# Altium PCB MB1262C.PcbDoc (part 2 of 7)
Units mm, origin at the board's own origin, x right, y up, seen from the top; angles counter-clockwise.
Board outline 208 x 250 mm, 6 copper layers (Top Layer, Layer 2, Layer 3, Layer 4, Layer 5, Bottom Layer), stack 1.596 mm thick; 483 components, 502 nets, 2134 pads, 1709 vias.
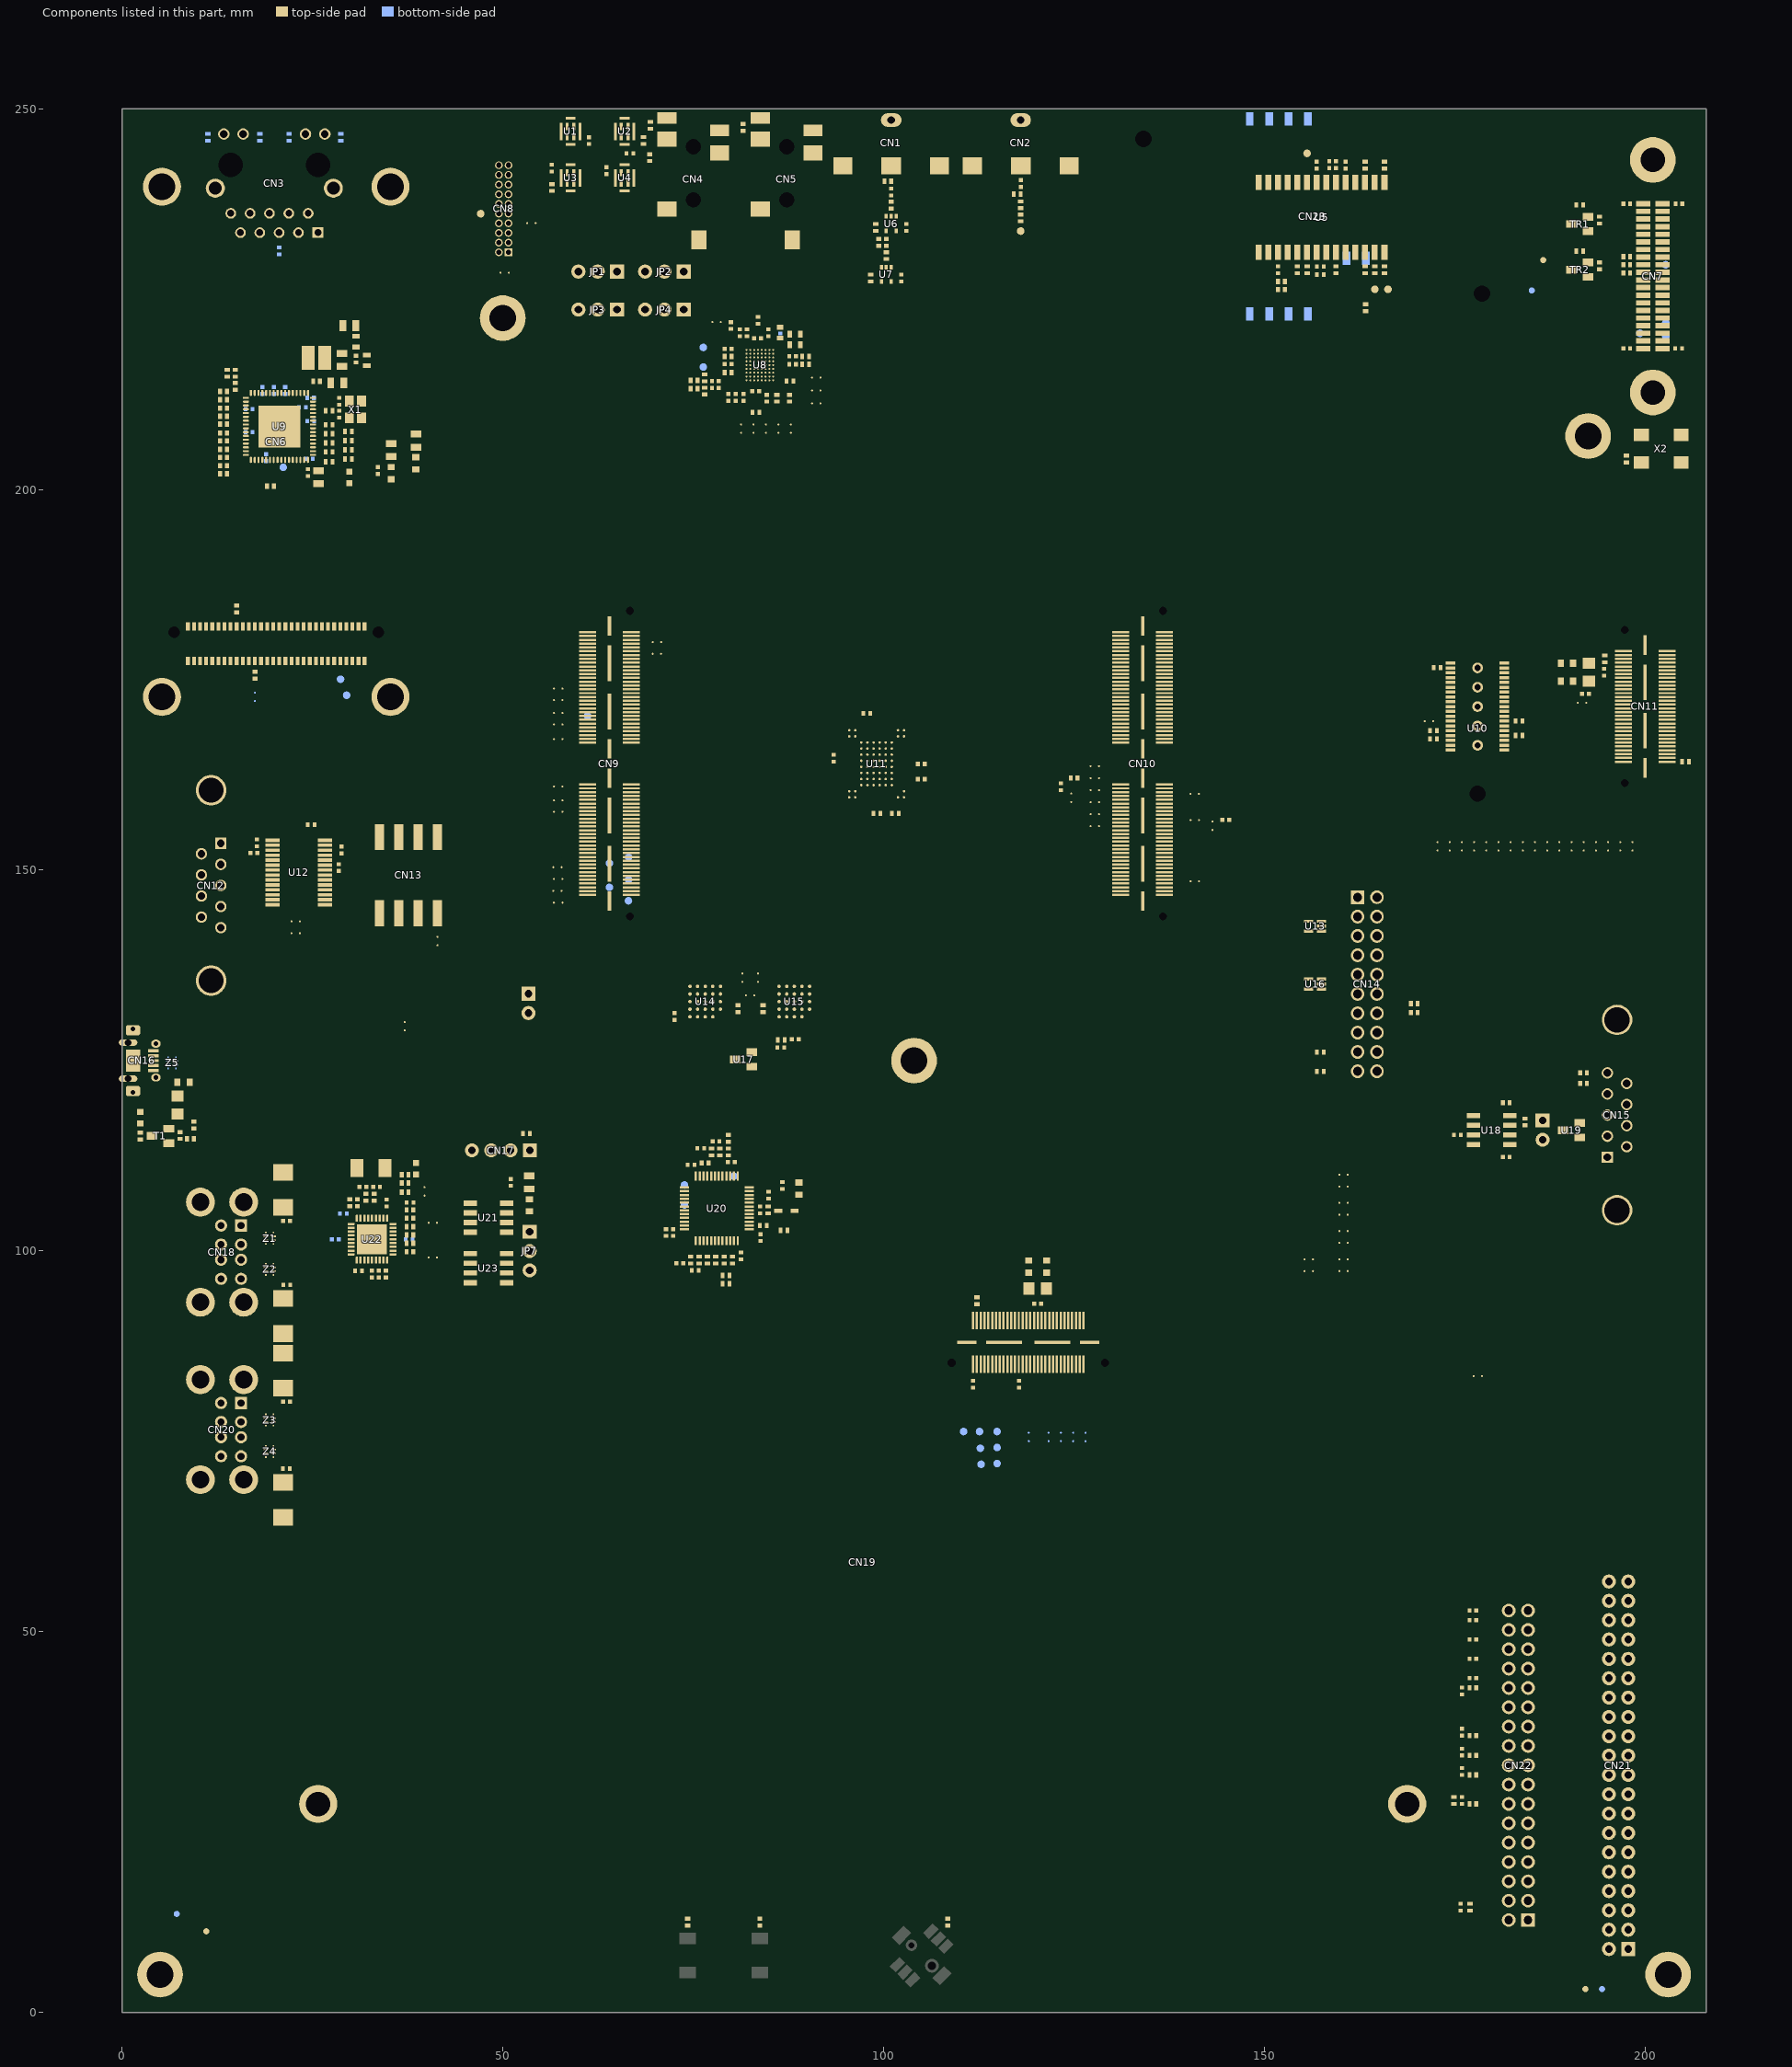
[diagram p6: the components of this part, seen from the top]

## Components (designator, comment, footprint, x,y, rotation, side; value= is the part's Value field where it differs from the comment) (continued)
C132 ".designator" C0402 29.067,104.935 r0 bottom value=100nF
C133 ".designator" C0402 37.7,101.55 r180 bottom value=100nF
C134 ".designator" C0402 28,101.55 r0 bottom value=100nF
CN1 ".designator" CON_SMD-RCA-SOCKET_CUI_RCJ-013-SMT 101,248.5 r270 top
CN2 ".designator" CON_SMD-RCA-SOCKET_CUI_RCJ-013-SMT 118,248.5 r270 top
CN3 ".designator" CON_RJ45_YD_48F-01GYDXNL_LED-P 20,250 r180 top locked
CN4 ".designator" CON_PHONE-JACK-3P5_HY_PJ3028B 75,250 r270 top value=PJ3028B-3_GR
CN5 ".designator" CON_PHONE-JACK-3P5_HY_PJ3028B 87.261,250 r270 top value="PJ-3028B-3 4P"
CN6 ".designator" CON_SAMTEC_ERF8-030-070-L-DV-TR_MOD-B2123A 20.25,179.75 r270 top locked
CN7 ".designator" CON_SAMTEC_CLM-120-02-L-D_Reverse-to-Camera 201,228 r0 top locked value=CLM-120-02-L-D
CN8 ".designator" CON_FCI_20021311-XXX20XXLF_MOD-MB1299 50.117,236.851 r270 top locked value="Receptacle 10X2 TH VT 1.27mm"
CN9 ".designator" CON_SAMTEC_QSH-060-01-L-D-A 64,164 r270 top locked
CN10 ".designator" CON_SAMTEC_QSH-060-01-L-D-A 134,164 r270 top locked
CN11 ".designator" CON_SAMTEC_QSH-030-01-F-D-A 200,171.5 r270 top locked value=QSH-030-01-F-D-A
CN12 ".designator" CON_DB9-MALE_TYCO_3-1634580-2 4.2,148 r270 top locked
CN13 ".designator" CON_SAMTEC_SSM-104-L-DH 37.625,149.35 r180 top locked value=SSM-104-L-DH
CN14 ".designator" CON_CVILUX_CH87-20-2-V-1-00 163.5,135.025 r270 top locked
CN15 ".designator" CON_DB9-MALE_TYCO_3-1634580-2 203.8,117.85 r90 top locked
CN16 ".designator" CON_USBMICROAB_MOLEX_47590-0001_H3 0,125 r270 top locked value=475900001
CN17 ".designator" CON_SAMTEC_TSW-104-07-G-S 49.75,113.219 r180 top locked value="Header 4 pins"
CN18 ".designator" CON_DUAL-USB-TYPE-A_CONEXCON_5600-3081 0,99.85 r270 top locked value="Dual USB Type A"
CN19 ".designator" CON_SAMTEC_QSH-030-01-F-D-A_LCD-MB1230 119,88 r180 top locked value=QSH-030-01-F-D-A
CN20 ".designator" CON_DUAL-USB-TYPE-A_CONEXCON_5600-3081 0,76.55 r270 top locked value="Dual USB Type A"
CN21 ".designator" CON_SAMTEC_TSW-120-07-G-D 196.5,32.475 r90 top locked value=TSW-120-07-G-D
CN22 ".designator" CON_SAMTEC_TST-117-01-T-D 183.35,32.475 r90 top locked value=BHFS03-34G01BT1
CN23 ".designator" CON_SMARTCARD_CONCRAFT_093A-65-08A 155,250 r0 bottom locked value=093A-65-08A
D1 ".designator" DIO_SOD323 87.25,105.3 r0 top
Designator1 ".designator" MOD_MB1263 64,164 r270 top locked
Designator2 ".designator" CARTOUCHE_STM_BOTTOM 43.172,-35.703 r0 top
Designator3 ".designator" CARTOUCHE_STM_TOP 43.097,-35.728 r0 top
H1 ".designator" PTH_M1261-3005-N_3P5X6_M3_H14 50,222.5 r180 bottom
H2 ".designator" PTH_M1261-3005-N_3P5X6_M3_H14 192.5,207 r180 bottom
H3 ".designator" PTH_M1261-3005-N_3P5X6_M3_H14 104,125 r180 bottom
H4 ".designator" PTH_M1261-3005-N_3P5X6_M3_H14 203,5 r180 bottom
H5 ".designator" PTH_M1261-3005-N_3P5X6_M3_H14 5,5 r180 bottom
JP1 ".designator" CON_SAMTEC_TSW-103-07-F-S 62.455,228.607 r180 top value="Header 3 pins"
JP2 ".designator" CON_SAMTEC_TSW-103-07-F-S 71.224,228.607 r180 top value="Header 3 pins"
JP3 ".designator" CON_SAMTEC_TSW-103-07-F-S 62.455,223.607 r180 top value="Header 3 pins"
JP4 ".designator" CON_SAMTEC_TSW-103-07-F-S 71.224,223.607 r180 top value="Header 3 pins"
JP5 ".designator" CON_SAMTEC_TSW-102-07-G-S 53.37,132.51 r270 top value=Jumper_2.54mm
JP6 ".designator" CON_SAMTEC_TSW-102-07-G-S 186.525,115.875 r270 top value=Jumper_2.54mm
JP7 ".designator" CON_SAMTEC_TSW-103-07-F-S 53.522,100 r270 top value="Header 3 pins"
L1 ".designator" L0603 38.56,203.436 r270 top value=100R
L2 ".designator" L0603 35.341,202.139 r270 top value=100R
L3 ".designator" L0603 189.725,177.175 r180 top value=600R
L4 ".designator" L0603 189.725,174.825 r180 top value=600R
L5 ".designator" FIL_0603_H065 8.074,122.143 r180 top value=120R
L6 ".designator" L0603 88.9,108.2 r270 top value=600R
L7 ".designator" FIL_0603_H065 53.48,106 r270 top value=26R
L8 ".designator" L0603 119.05,97.95 r270 top value=600R
L9 ".designator" L0603 121.4,97.95 r270 top value=600R
LD1 ".designator" LED_0603_GREEN 29.842,201.588 r90 top value="LED, Green, 0603"
LD2 ".designator" LED_0603_GREEN 2.395,117.514 r90 top value="LED, Green"
LD3 ".designator" LED_0603_RED 38.59,110.792 r90 top value="LED, Red, 0603"
LE1 ".designator" L1210_LQH 25.54,217.278 r0 top
MIRE1 ".designator" MIRE_PLACE_SMD_0P8MM 186.604,230.116 r270 top
MIRE2 ".designator" MIRE_PLACE_SMD_0P8MM 11.067,10.678 r270 top
MIRE3 ".designator" MIRE_PLACE_SMD_0P8MM 192.147,3.091 r270 top
MIRE4 "MIRE4" MIRE_PLACE_SMD_0P8MM 185.099,226.124 r90 bottom
MIRE5 "MIRE5" MIRE_PLACE_SMD_0P8MM 7.179,12.964 r90 bottom
MIRE6 "MIRE6" MIRE_PLACE_SMD_0P8MM 194.326,3.091 r90 bottom
R1 ".designator" R0402 69.359,247.804 r90 top value=0R
R2 ".designator" R0402 81.535,247.523 r270 top value=1K
R3 ".designator" R0402 68.475,245.8 r270 top value=10K
R4 ".designator" R0402 69.291,243.56 r270 top value=0R
R5 ".designator" R0402 163.225,242.575 r270 top value=100K
R6 ".designator" R0402 165.75,242.575 r90 top value=4K7
R7 ".designator" R0402 100.55,240.45 r0 top value=75
R8 ".designator" R0402 56.448,239.635 r90 top value=10K
R9 ".designator" R0402 117.55,238.775 r180 top value=110
R10 ".designator" R0402 118,237.375 r90 top value=210
R11 ".designator" R0402 101,237.325 r270 top value="100R 1%"
R12 ".designator" R0402 191.4,237.35 r0 top value=1K
R13 ".designator" R0402 118,235.65 r90 top value=0R
R14 ".designator" R0402 194,235.375 r270 top value=4K7
R15 ".designator" R0402 98.95,234.4 r270 top value=1M
R16 ".designator" R0402 99.35,232.425 r270 top value=0R
R17 ".designator" R0402 191.4,231.3 r0 top value=1K
R18 ".designator" R0402 100.35,230.7 r270 top value="100R 1%"
R19 ".designator" R0402 197.575,230.575 r0 top value=10K
R20 ".designator" R0402 194,229.35 r270 top value=4K7
R21 ".designator" R0402 197.575,229.5 r0 top value=1K
R22 ".designator" R0402 154.325,228.85 r270 top value=100K
R23 ".designator" R0402 155.6,228.85 r270 top value=100K
R24 ".designator" R0402 159.4,228.85 r90 top value=100K
R25 ".designator" R0402 163.225,228.85 r270 top value=0R
R26 ".designator" R0402 164.5,228.85 r90 top value=10K
R27 ".designator" R0402 165.75,228.85 r90 top value=10K
R28 ".designator" R0402 197.575,228.425 r0 top value=1K
R29 ".designator" R0402 98.3,227.75 r270 top value=1M
R30 ".designator" R0402 152.225,227.3 r180 top value=10K
R31 ".designator" R0402 152.225,226.25 r0 top value=10K
R32 ".designator" R0402 163.298,223.855 r90 top value=100K
R33 ".designator" R0603 30.731,219.407 r270 top value=0R_0603
R34 ".designator" R0603 32.133,216.939 r90 top value=0R_0603
R35 ".designator" R0402 79.575,217.475 r180 top value=2K2
R36 ".designator" R0402 89.75,217.475 r180 top value="20R 1%"
R37 ".designator" R0402 89.75,216.425 r180 top value="20R 1%"
R38 ".designator" R0402 13.825,215.25 r90 top value=4K7
R39 ".designator" R0402 14.875,215.25 r270 top value=4K7
R40 ".designator" R0402 79.575,215.35 r0 top value=4K7
R41 ".designator" R0402 76.504,214.638 r270 top value=1K
R42 ".designator" R0402 75.104,214.313 r180 top value="180R 1%"
R43 ".designator" R0402 87.711,214.22 r0 top value=1K
R44 ".designator" R0402 25.544,214.182 r180 top value="22R 1%"
R45 ".designator" R0402 14.875,213.525 r270 top value=0R
R46 ".designator" R0402 75.104,213.238 r180 top value="180R 1%"
R47 ".designator" R0402 76.504,212.913 r270 top value=1K
R48 ".designator" R0402 13.325,212.875 r0 top value="22R 1%"
R49 ".designator" R0402 85.98,211.975 r270 top value=0R
R50 ".designator" R0402 87.633,211.975 r270 top value=0R
R51 ".designator" R0402 13.325,211.775 r0 top value="22R 1%"
R52 ".designator" R0402 13.325,210.675 r0 top value="22R 1%"
R53 ".designator" R0402 27.189,210.321 r180 top value=0R
R54 ".designator" R0402 83.242,210.125 r0 top value=0R
R55 ".designator" R0402 13.325,209.6 r0 top value="22R 1%"
R56 ".designator" R0402 13.325,208.575 r0 top value=0R
R57 ".designator" R0402 27.187,208.497 r180 top value=2K49
R58 ".designator" R0402 29.737,207.628 r0 top value=4K7
R59 ".designator" R0402 13.325,207.4 r180 top value=4K7
R60 ".designator" R0402 27.187,207.306 r0 top value=1K5
R61 ".designator" R0402 29.737,206.413 r0 top value=4K7
R62 ".designator" R0402 13.325,206.375 r180 top value=4K7
R63 ".designator" R0402 27.187,206.116 r0 top value=1K5
R64 ".designator" R0402 13.325,205.275 r180 top value=4K7
R65 ".designator" R0402 29.737,205.197 r180 top value=0R
R66 ".designator" R0402 27.187,204.925 r0 top value=1K5
R67 ".designator" R0402 197.525,204 r270 top value=10K
R68 ".designator" R0402 13.325,204.2 r180 top value=4K7
R69 ".designator" R0402 29.737,203.981 r180 top value=0R
R70 ".designator" R0402 27.187,203.634 r0 top value="510R 1%"
R71 ".designator" R0402 13.325,203.125 r180 top value=4K7
R72 ".designator" R0402 13.325,202.05 r180 top value=4K7
R73 ".designator" R0402 19.486,200.412 r180 top value=0R
R74 ".designator" R0402 15.046,184.311 r270 top value=0R
R75 ".designator" R0402 194.675,177.75 r270 top value=0R
R76 ".designator" R0402 172.688,176.613 r180 top value=0R
R77 ".designator" R0402 17.457,175.615 r90 top value=0R
R78 ".designator" R0402 183.425,169.6 r180 top value=10K
R79 ".designator" R0402 172.2,168.325 r180 top value=10K
R80 ".designator" R0402 183.425,167.7 r180 top value=10K
R81 ".designator" R0402 172.2,167.25 r180 top value=10K
R82 ".designator" R0402 205.3,164.25 r0 top value=0R
R83 ".designator" R0402 125.009,162.096 r180 top value=0R
R84 ".designator" R0402 99.125,157.45 r0 top value=10K
R85 ".designator" R0402 101.525,157.45 r0 top value=10K
R86 ".designator" R0402 169.675,132.5 r180 top value=10K
R87 ".designator" R0402 84.187,131.82 r90 top value=10K
R88 ".designator" R0402 80.881,131.82 r90 top value=10K
R89 ".designator" R0402 169.675,131.3 r0 top value=10K
R90 ".designator" R0402 86.557,127.717 r0 top value=15K
R91 ".designator" R0402 157.325,126.125 r180 top value=10K
R92 ".designator" R0402 157.325,123.575 r180 top value=10K
R93 ".designator" R0402 191.9,123.4 r0 top value=0R
R94 ".designator" R0402 191.9,122 r0 top value=1K
R95 ".designator" R0402 181.75,119.475 r0 top value=10K
R96 ".designator" R0402 184.2,116.95 r90 top value="120R 1%"
R97 ".designator" R0402 9.43,116.537 r90 top value=0R
R98 ".designator" R0402 7.621,115.164 r90 top value=10K
R99 ".designator" R0402 53.097,115.42 r180 top value=0R
R100 ".designator" R0402 2.384,115.097 r270 top value=330R
R101 ".designator" R0402 79.6,114.8 r90 top value=10K
R102 ".designator" R0402 8.987,114.72 r180 top value=47K
R103 ".designator" R0402 77.4,113 r90 top value=0R
R104 ".designator" R0402 78.5,113 r90 top value=0R
R105 ".designator" R0402 79.6,113 r270 top value=10K
R106 ".designator" R0402 76.565,111.549 r180 top value="100R 1%"
R107 ".designator" R0402 37.175,110.015 r0 top value=1K
R108 ".designator" R0402 37.175,108.93 r180 top value=100K
R109 ".designator" R0402 37.175,107.736 r180 top value=10K
R110 ".designator" R0402 32.012,107.052 r270 top value=0R
R111 ".designator" R0402 33.112,107.052 r270 top value=0R
R112 ".designator" R0402 29.913,106.346 r90 top value=12K
R113 ".designator" R0402 84.825,105.4 r90 top value=10K
R114 ".designator" R0402 37.806,105.405 r180 top value=100K
R115 ".designator" R0402 37.806,104.305 r0 top value=100K
R116 ".designator" R0402 84.21,103.34 r180 top value=47K
R117 ".designator" R0402 37.806,103.205 r180 top value=100K
R118 ".designator" R0402 86.925,102.71 r180 top value=0R
R119 ".designator" R0402 37.806,102.105 r0 top value=100K
R120 ".designator" R0402 37.806,101.005 r0 top value=100K
R121 ".designator" R0402 37.806,99.905 r180 top value=100K
R122 ".designator" R0402 74.66,98.823 r270 top value=0R
R123 ".designator" R0402 75.76,98.823 r270 top value=0R
R124 ".designator" R0402 76.86,98.823 r90 top value=0R
R125 ".designator" R0402 77.96,98.823 r90 top value=0R
R126 ".designator" R0402 79.06,98.823 r90 top value="510R 1%"
R127 ".designator" R0402 80.16,98.823 r90 top value=0R
R128 ".designator" R0402 79.31,96.798 r180 top value=10K
R129 ".designator" R0402 79.31,95.698 r180 top value=1K
R130 ".designator" R0402 112.25,93.475 r90 top value=10K
R131 ".designator" R0402 177.368,42.644 r180 top value=0R
R132 ".designator" R0402 177.368,36.38 r0 top value=0R
R133 ".designator" R0402 177.368,33.765 r0 top value=0R
R134 ".designator" R0402 177.368,31.201 r0 top value=0R
R135 ".designator" R0402 174.873,27.844 r270 top value=100K
R136 ".designator" R0402 177.368,27.394 r180 top value=0R
R137 ".designator" R0402 176.98,13.835 r90 top value=3K3
R138 ".designator" R0402 108.426,11.886 r270 top value=100R
R139 ".designator" R0402 74.25,11.875 r270 top value=10K
R140 ".designator" R0402 28.722,246.23 r270 bottom value="510R 1%"
R141 ".designator" R0402 21.929,246.23 r90 bottom value=4K7
R142 ".designator" R0402 11.285,246.223 r90 bottom value=4K7
R143 ".designator" R0402 18.096,246.223 r270 bottom value="510R 1%"
SB1 ".designator" SOLDER-BRIDGE_R0603-0R 53.805,234.949 r180 top value=SB_OFF
SB2 ".designator" SOLDER-BRIDGE_R0603-0R 50.197,228.46 r0 top value=SB_ON
SB3 ".designator" SOLDER-BRIDGE_R0603-0R 78.008,221.965 r0 top value=SB_ON
SB4 ".designator" SOLDER-BRIDGE_R0603-0R 91.2,214.7 r180 top value=SB_OFF
SB5 ".designator" SOLDER-BRIDGE_R0603-0R 91.2,213 r180 top value=SB_ON
SB6 ".designator" SOLDER-BRIDGE_R0603-0R 91.2,211.3 r180 top value=SB_ON
SB7 ".designator" SOLDER-BRIDGE_R0603-0R 81.291,207.934 r90 top value=SB_ON
SB8 ".designator" SOLDER-BRIDGE_R0603-0R 84.556,207.934 r90 top value=SB_ON
SB9 ".designator" SOLDER-BRIDGE_R0603-0R 86.189,207.934 r90 top value=SB_ON
SB10 ".designator" SOLDER-BRIDGE_R0603-0R 87.821,207.934 r90 top value=SB_ON
SB11 ".designator" SOLDER-BRIDGE_R0603-0R 82.923,207.934 r90 top value=SB_ON
SB12 ".designator" SOLDER-BRIDGE_R0603-0R 70.293,179.951 r180 top value=SB_OFF
SB13 ".designator" SOLDER-BRIDGE_R0603-0R 70.293,178.413 r180 top value=SB_OFF
SB14 ".designator" SOLDER-BRIDGE_R0603-0R 57.217,173.842 r0 top value=SB_OFF
SB15 ".designator" SOLDER-BRIDGE_R0603-0R 57.217,172.338 r0 top value=SB_ON
SB16 ".designator" SOLDER-BRIDGE_R0603-0R 191.65,172 r0 top value=SB_ON
SB17 ".designator" SOLDER-BRIDGE_R0603-0R 57.217,170.634 r0 top value=SB_ON
SB18 ".designator" SOLDER-BRIDGE_R0603-0R 171.65,169.575 r180 top value=SB_OFF
SB19 ".designator" SOLDER-BRIDGE_R0603-0R 57.217,169.129 r0 top value=SB_OFF
SB20 ".designator" SOLDER-BRIDGE_R0603-0R 57.217,167.225 r0 top value=SB_OFF
SB21 ".designator" SOLDER-BRIDGE_R0603-0R 127.683,163.672 r0 top value=SB_OFF
SB22 ".designator" SOLDER-BRIDGE_R0603-0R 127.683,162.093 r0 top value=SB_OFF
SB23 ".designator" SOLDER-BRIDGE_R0603-0R 57.217,160.998 r0 top value=SB_OFF
SB24 ".designator" SOLDER-BRIDGE_R0603-0R 127.683,160.513 r0 top value=SB_OFF
SB25 ".designator" SOLDER-BRIDGE_R0603-0R 124.615,159.561 r270 top value=SB_OFF
SB26 ".designator" SOLDER-BRIDGE_R0603-0R 140.893,160.026 r180 top value=SB_OFF
SB27 ".designator" SOLDER-BRIDGE_R0603-0R 57.217,159.163 r0 top value=SB_ON
SB28 ".designator" SOLDER-BRIDGE_R0603-0R 127.683,158.933 r0 top value=SB_OFF
SB29 ".designator" SOLDER-BRIDGE_R0603-0R 57.217,157.692 r0 top value=SB_OFF
SB30 ".designator" SOLDER-BRIDGE_R0603-0R 127.683,157.354 r0 top value=SB_OFF
SB31 ".designator" SOLDER-BRIDGE_R0603-0R 143.186,155.887 r270 top value=SB_OFF
SB32 ".designator" SOLDER-BRIDGE_R0603-0R 140.903,156.582 r180 top value=SB_OFF
SB33 ".designator" SOLDER-BRIDGE_R0603-0R 127.683,155.774 r0 top value=SB_OFF
SB34 ".designator" SOLDER-BRIDGE_R0603-0R 198.326,153.092 r90 top value=SB_ON
SB35 ".designator" SOLDER-BRIDGE_R0603-0R 174.326,153.092 r90 top value=SB_ON
SB36 ".designator" SOLDER-BRIDGE_R0603-0R 182.326,153.092 r90 top value=SB_ON
SB37 ".designator" SOLDER-BRIDGE_R0603-0R 196.726,153.092 r90 top value=SB_ON
SB38 ".designator" SOLDER-BRIDGE_R0603-0R 172.726,153.092 r90 top value=SB_ON
SB39 ".designator" SOLDER-BRIDGE_R0603-0R 177.526,153.092 r90 top value=SB_ON
SB40 ".designator" SOLDER-BRIDGE_R0603-0R 179.126,153.092 r90 top value=SB_ON
SB41 ".designator" SOLDER-BRIDGE_R0603-0R 180.726,153.092 r90 top value=SB_ON
SB42 ".designator" SOLDER-BRIDGE_R0603-0R 183.926,153.092 r90 top value=SB_ON
SB43 ".designator" SOLDER-BRIDGE_R0603-0R 185.526,153.092 r90 top value=SB_ON
SB44 ".designator" SOLDER-BRIDGE_R0603-0R 188.726,153.092 r90 top value=SB_ON
SB45 ".designator" SOLDER-BRIDGE_R0603-0R 190.326,153.092 r90 top value=SB_ON
SB46 ".designator" SOLDER-BRIDGE_R0603-0R 191.926,153.092 r90 top value=SB_ON
SB47 ".designator" SOLDER-BRIDGE_R0603-0R 193.526,153.092 r90 top value=SB_ON
SB48 ".designator" SOLDER-BRIDGE_R0603-0R 195.126,153.092 r90 top value=SB_ON
SB49 ".designator" SOLDER-BRIDGE_R0603-0R 175.926,153.092 r90 top value=SB_ON
SB50 ".designator" SOLDER-BRIDGE_R0603-0R 187.126,153.092 r90 top value=SB_ON
SB51 "SB47" SOLDER-BRIDGE_R0603-0R 57.217,150.392 r180 top value=SB_ON
SB52 ".designator" SOLDER-BRIDGE_R0603-0R 57.217,148.842 r0 top value=SB_OFF
SB53 ".designator" SOLDER-BRIDGE_R0603-0R 140.903,148.561 r180 top value=SB_OFF
SB54 ".designator" SOLDER-BRIDGE_R0603-0R 57.217,147.292 r180 top value=SB_ON
SB55 ".designator" SOLDER-BRIDGE_R0603-0R 57.217,145.742 r0 top value=SB_OFF
SB56 ".designator" SOLDER-BRIDGE_R0603-0R 22.85,143.275 r180 top value=SB_OFF
SB57 ".designator" SOLDER-BRIDGE_R0603-0R 22.85,141.725 r180 top value=SB_ON
SB58 ".designator" SOLDER-BRIDGE_R0603-0R 41.425,140.75 r270 top value=SB_OFF
SB59 ".designator" SOLDER-BRIDGE_R0603-0R 81.455,135.944 r270 top value=SB_ON
SB60 ".designator" SOLDER-BRIDGE_R0603-0R 83.508,135.944 r270 top value=SB_ON
SB61 ".designator" SOLDER-BRIDGE_R0603-0R 82.515,133.566 r180 top value=SB_OFF
SB62 ".designator" SOLDER-BRIDGE_R0603-0R 37.11,129.566 r270 top value=SB_ON
SB63 ".designator" SOLDER-BRIDGE_R0603-0R 160.437,110.023 r180 top value=SB_OFF
SB64 ".designator" SOLDER-BRIDGE_R0603-0R 39.7,107.875 r270 top
SB65 ".designator" SOLDER-BRIDGE_R0603-0R 160.436,108.472 r180 top value=SB_OFF
SB66 ".designator" SOLDER-BRIDGE_R0603-0R 160.437,106.321 r180 top value=SB_OFF
SB67 ".designator" SOLDER-BRIDGE_R0603-0R 160.436,104.769 r180 top value=SB_OFF
SB68 ".designator" SOLDER-BRIDGE_R0603-0R 40.855,103.712 r180 top value=SB_OFF
SB69 ".designator" SOLDER-BRIDGE_R0603-0R 160.437,102.618 r180 top value=SB_OFF
SB70 ".designator" SOLDER-BRIDGE_R0603-0R 160.436,101.067 r180 top value=SB_OFF
SB71 ".designator" SOLDER-BRIDGE_R0603-0R 40.855,99.157 r180 top value=SB_OFF
SB72 ".designator" SOLDER-BRIDGE_R0603-0R 155.876,98.915 r180 top value=SB_OFF
SB73 ".designator" SOLDER-BRIDGE_R0603-0R 160.437,98.915 r180 top value=SB_OFF
SB74 ".designator" SOLDER-BRIDGE_R0603-0R 155.87,97.364 r180 top value=SB_OFF
SB75 ".designator" SOLDER-BRIDGE_R0603-0R 160.436,97.364 r180 top value=SB_OFF
SB76 ".designator" SOLDER-BRIDGE_R0603-0R 178.065,83.591 r180 top value=SB_OFF
SB77 ".designator" SOLDER-BRIDGE_R0603-0R 17.457,172.709 r90 bottom value=SB_ON
SB78 "SB73" SOLDER-BRIDGE_R0603-0R 126.525,75.625 r270 bottom value=SB_ON
SB79 "SB74" SOLDER-BRIDGE_R0603-0R 124.9,75.625 r270 bottom value=SB_ON
SB80 "SB75" SOLDER-BRIDGE_R0603-0R 123.275,75.625 r270 bottom value=SB_ON
SB81 "SB76" SOLDER-BRIDGE_R0603-0R 121.65,75.625 r270 bottom value=SB_ON
SB82 "SB77" SOLDER-BRIDGE_R0603-0R 119.05,75.625 r270 bottom value=SB_ON
T1 ".designator" NPN_SOT23 5.045,115.111 r90 top value=BSR14
TP1 ".designator" TP_SMD_1MM 155.6,244.125 r0 top value=TP
TP2 ".designator" TP_SMD_1MM 47.099,236.199 r270 top value=TP
TP3 ".designator" TP_SMD_1MM 118,233.925 r0 top value=TP
TP4 ".designator" TP_SMD_1MM 164.5,226.275 r0 top value=TP
TP5 ".designator" TP_SMD_1MM 166.225,226.275 r0 top value=TP
TP6 ".designator" TP_SMD_1MM 202.675,229.5 r0 bottom value=TP
TP7 ".designator" TP_SMD_1MM 202.7,221.925 r0 bottom value=TP
TP8 ".designator" TP_SMD_1MM 199.3,220.5 r0 bottom value=TP
TP9 ".designator" TP_SMD_1MM 202.7,220.075 r0 bottom value=TP
TP10 "TP10" TP_SMD_1MM 76.322,218.644 r90 bottom value=TP
TP11 ".designator" TP_SMD_1MM 76.322,216.069 r90 bottom value=TP
TP12 ".designator" TP_SMD_1MM 21.169,202.901 r0 bottom value=TP
TP13 ".designator" TP_SMD_1MM 28.7,175.075 r0 bottom value=TP
TP14 ".designator" TP_SMD_1MM 29.5,172.975 r0 bottom value=TP
TP15 ".designator" TP_SMD_1MM 61.125,170.275 r0 bottom value=TP
TP16 "TP16" TP_SMD_1MM 66.508,151.703 r180 bottom value=TP
TP17 "TP17" TP_SMD_1MM 63.991,150.92 r180 bottom value=TP
TP18 "TP18" TP_SMD_1MM 66.508,148.752 r180 bottom value=TP
TP19 "TP19" TP_SMD_1MM 63.991,147.752 r180 bottom value=TP
TP20 "TP20" TP_SMD_1MM 66.492,145.985 r180 bottom value=TP
TP21 ".designator" TP_SMD_1MM 80.35,109.825 r0 bottom value=TP
TP22 ".designator" TP_SMD_1MM 73.85,108.675 r0 bottom value=TP
TP23 ".designator" TP_SMD_1MM 73.85,106.05 r0 bottom value=TP
TP24 ".designator" TP_SMD_1MM 114.9,76.3 r0 bottom value=TP
TP25 ".designator" TP_SMD_1MM 112.6,76.3 r0 bottom value=TP
TP26 ".designator" TP_SMD_1MM 110.5,76.3 r0 bottom value=TP
TP27 ".designator" TP_SMD_1MM 114.9,74.2 r0 bottom value=TP
TP28 ".designator" TP_SMD_1MM 112.7,74.1 r0 bottom value=TP
TP29 ".designator" TP_SMD_1MM 114.9,72.1 r0 bottom value=TP
TP30 ".designator" TP_SMD_1MM 112.8,72 r0 bottom value=TP
TR1 ".designator" MOS_SOT23 191.4,234.85 r90 top value=BSN20
TR2 ".designator" MOS_SOT23 191.4,228.85 r90 top value=BSN20
U1 ".designator" MIC_HCLGA_3X4X1_4LD 58.888,247 r0 top locked value=MP34DT01TR-M
U2 ".designator" MIC_HCLGA_3X4X1_4LD 66,247 r0 top locked value=MP34DT01TR-M
U3 ".designator" MIC_HCLGA_3X4X1_4LD 58.888,240.904 r180 top locked value=MP34DT01TR-M
U4 ".designator" MIC_HCLGA_3X4X1_4LD 66,240.904 r180 top locked value=MP34DT01TR-M
U5 ".designator" ICC_SO28_18P10X7P60_P127 157.5,235.725 r180 top locked
U6 ".designator" DIO_SOT353 101,234.9 r180 top
U7 ".designator" DIO_SOT353 100.35,228.25 r180 top
U8 ".designator" ICC_W-CSP-BGA72_4P511X4P023_P050 83.75,216.325 r90 top locked value=WM8994ECS/R
U9 ".designator" ICC_QFN64-EPAD_9X9_P050 20.675,208.275 r270 top locked
U10 ".designator" CON_MICTOR_TYCO_2-5767004-2 177.985,171.485 r270 top locked
U11 ".designator" ICC_VFBGA63_9X11_P080 99.075,163.975 r180 top locked
U12 ".designator" ICC_SSOP28_10P2X5P3_P065 23.2,149.7 r270 top value=ST3241EBPR
U13 ".designator" ESD_SOT323-5L 156.65,142.65 r90 top locked
U14 ".designator" ICC_BGA24_5X5-BALL-ARRAY_6X8_P1 76.575,132.75 r180 top
U15 ".designator" ICC_BGA24_5X5-BALL-ARRAY_6X8_P1 88.275,132.75 r180 top
U16 ".designator" ESD_SOT323-5L 156.65,135.05 r90 top locked
U17 ".designator" MOS_SOT23 81.6,125.15 r90 top
U18 ".designator" ICC_SO8_5X4_P127 179.825,115.875 r270 top value=MCP2562FDT-H/SN
U19 ".designator" ESD_SOT23 190.3,115.85 r90 top value=ESDCAN24-2BLY
U20 ".designator" ICC_LQFP48_7X7_P050 78.1,105.6 r90 top value=STM32L152CCT6
U21 ".designator" ICC_SO8_5X4_P127 48.115,104.387 r90 top value=STMPS2252MTR
U22 ".designator" ICC_QFN36-EPAD_6X6_P050 32.825,101.55 r270 top value=USB2514B-AEZC
U23 ".designator" ICC_SO8_5X4_P127 48.115,97.749 r90 top value=STMPS2252MTR
X1 ".designator" CRY_NX3225HA_4P 30.65,210.5 r90 top value=25MHz
X2 ".designator" OSC_PLE_SM77H-SERIES_7X5_H1P73_4P 202.1,205.35 r0 top
X3 ".designator" CRY_TXC_7A-SERIES_5X3P2_H1P2_2P 32.67,110.902 r180 top value=24MHz
Z1 ".designator" ESD_UQFN-8L_2P5X1P2_P050 19.392,101.674 r270 top value=ECMF02-4CMX8
Z2 ".designator" ESD_UQFN-8L_2P5X1P2_P050 19.392,97.599 r270 top value=ECMF02-4CMX8
Z3 ".designator" ESD_UQFN-8L_2P5X1P2_P050 19.392,77.812 r270 top value=ECMF02-4CMX8
Z4 ".designator" ESD_UQFN-8L_2P5X1P2_P050 19.392,73.687 r270 top value=ECMF02-4CMX8
Z5 "Z1" ESD_UQFN-8L_2P5X1P2_P050 6.574,124.713 r90 bottom value=ECMF02-4CMX8

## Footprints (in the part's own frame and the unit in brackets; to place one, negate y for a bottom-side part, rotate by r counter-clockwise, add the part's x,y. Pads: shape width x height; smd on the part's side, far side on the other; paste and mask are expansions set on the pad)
C0402 [mm]
  rect 0.51x0.56 smd mask+0.05: 1(-0.45,0) 2(0.45,0)
  silkscreen extent -0.72,-0.35 0.72,0.35, body extent -0.5,-0.3 0.5,0.3, height 0.4
C0603 [mm]
  rect 0.64x0.89 smd mask+0.05: 1(-0.7,0) 2(0.7,0)
  silkscreen extent -1.05,-0.55 1.02,0.55, body extent -0.9,-0.5 0.9,0.5, height 1.4
C0805 [mm]
  rect 0.9x1.4 smd mask+0.05: 1(-0.85,0) 2(0.85,0)
  silkscreen extent -1.3,-0.77 1.3,0.77, body extent -1.1,-0.7 1.1,0.7, height 1.35
CARTOUCHE_STM_BOTTOM [mm]
CARTOUCHE_STM_TOP [mm]
CON_CVILUX_CH87-20-2-V-1-00 [mm]
  rect 1.8x1.8 hole 1.2 mask+0.05: 1(-11.43,-1.27)
  round 1.8 hole 1.2 mask+0.05: 2(-11.43,1.27) 3(-8.89,-1.27) 4(-8.89,1.27) 5(-6.35,-1.27) 6(-6.35,1.27) 7(-3.81,-1.27) 8(-3.81,1.27) 9(-1.27,-1.27) 10(-1.27,1.27) 11(1.27,-1.27) 12(1.27,1.27) 13(3.81,-1.27) 14(3.81,1.27) 15(6.35,-1.27) 16(6.35,1.27) 17(8.89,-1.27) 18(8.89,1.27) 19(11.43,-1.27) 20(11.43,1.27)
  silkscreen extent -16.51,-4.55 16.51,4.55, body extent -16.51,-4.57 16.51,4.57, height 9.86
CON_DB9-MALE_TYCO_3-1634580-2 [mm]
  rect 1.5x1.5 / inner round 1.5 / far side rect 1.5x1.5 hole 1 mask+0.05: 1(-5.54,8.77)
  round 1.5 hole 1 mask+0.05: 2(-2.77,8.77) 3(0,8.77) 4(2.77,8.77) 5(5.54,8.77) 6(-4.155,6.23) 7(-1.385,6.23) 8(1.385,6.23) 9(4.155,6.23)
  round 4 hole 3.3 mask+0.05: MT1(-12.5,7.5) MT2(12.5,7.5)
  silkscreen extent -15.5,-10.3 15.5,10.6, body extent -15.5,-10.3 15.5,10.6, height 13.8
CON_DUAL-USB-TYPE-A_CONEXCON_5600-3081 [mm]
  round 1.6 hole 0.92: B1(-3.5,13.01) B2(-1,13.01) B3(1,13.01) B4(3.5,13.01) T2(-1,15.63) T3(1,15.63) T4(3.5,15.63)
  round 3.8 hole 2.33: CH1(6.57,10.3) CH2(-6.57,10.3) CH3(-6.57,15.98) CH4(6.57,15.98)
  rect 1.6x1.6 hole 0.92: T1(-3.5,15.63)
  silkscreen extent -7.3,-0.4 7.3,17.85, body extent -7.82,-0.6 7.88,17.85, height 16.2
CON_FCI_20021311-XXX20XXLF_MOD-MB1299 [mm] "MB1299 MICROPHONE MEMS"
  rect 1x1 / inner round 1 / far side rect 1x1 hole 0.7 mask+0.05: 1(5.715,0.635)
  round 1 hole 0.7 mask+0.05: 2(5.715,-0.635) 3(4.445,0.635) 4(4.445,-0.635) 5(3.175,0.635) 6(3.175,-0.635) 7(1.905,0.635) 8(1.905,-0.635) 9(0.635,0.635) 10(0.635,-0.635) 11(-0.635,0.635) 12(-0.635,-0.635) 13(-1.905,0.635) 14(-1.905,-0.635) 15(-3.175,0.635) 16(-3.175,-0.635) 17(-4.445,0.635) 18(-4.445,-0.635) 19(-5.715,0.635) 20(-5.715,-0.635)
  silkscreen extent -9.13,-6.99 9.27,7.01, body extent -9.13,-6.99 9.27,7.01, height 6.9
CON_MICTOR_TYCO_2-5767004-2 [mm]
  rect 0.43x1.27 smd mask+0.05: 1(5.715,3.53) 2(5.715,-3.53) 3(5.08,3.53) 4(5.08,-3.53) 5(4.445,3.53) 6(4.445,-3.53) 7(3.81,3.53) 8(3.81,-3.53) 9(3.175,3.53) 10(3.175,-3.53) 11(2.54,3.53) 12(2.54,-3.53) 13(1.905,3.53) 14(1.905,-3.53) 15(1.27,3.53) 16(1.27,-3.53) 17(0.635,3.53) 18(0.635,-3.53) 19(0,3.53) 20(0,-3.53) 21(-0.635,3.53) 22(-0.635,-3.53) 23(-1.27,3.53) 24(-1.27,-3.53) 25(-1.905,3.53) 26(-1.905,-3.53) 27(-2.54,3.53) 28(-2.54,-3.53) 29(-3.175,3.53) 30(-3.175,-3.53) 31(-3.81,3.53) 32(-3.81,-3.53) 33(-4.445,3.53) 34(-4.445,-3.53) 35(-5.08,3.53) 36(-5.08,-3.53) 37(-5.715,3.53) 38(-5.715,-3.53)
  round 1.4 hole 0.81 mask+0.05: MT1(-5.08,0) MT2(-2.54,0) MT3(0,0) MT4(2.54,0) MT5(5.08,0)
  round 0.5 hole 2.1 unplated mask+0.1: MT6(11.43,0)
  Multi-Layer keep-out circle w0.01: c11.43,0 r1.3
  silkscreen extent -12.7,-3.47 12.7,3.47, body extent -12.7,-4.36 12.7,4.36, height 6.35
CON_PHONE-JACK-3P5_HY_PJ3028B [mm]
  rect 1.5x2.5 smd mask+0.05: 2(1.25,-3.45) 7(2.85,3.45)
  rect 2x2.5 smd mask+0.05: 3(4,-3.45) 4(5.8,3.45) 6(13.2,-3.45)
  rect 2.5x2 smd mask+0.05: 5(17.25,0.75)
  round 0.5 hole 2 unplated mask+0.1: MT1(5,0) MT2(12,0)
  Multi-Layer keep-out circle w0.01: c5,0 r1.25
  Multi-Layer keep-out circle w0.01: c12,0 r1.25
  silkscreen extent -0.9,-3.7 16,3, body extent -0.9,-3 16,3, height 5
CON_RJ45_YD_48F-01GYDXNL_LED-P [mm]
  rect 1.4x1.4 hole 0.9 mask+0.05: 1(-5.715,16.29)
  round 1.4 hole 0.9 mask+0.05: 2(-4.445,13.75) 3(-3.175,16.29) 4(-1.905,13.75) 5(-0.635,16.29) 6(0.635,13.75) 7(1.905,16.29) 8(3.175,13.75) 9(4.445,16.29) 10(5.715,13.75)
  round 1.5 hole 1 mask+0.05: 11(-6.63,3.34) 12(-4.09,3.34) 13(4.09,3.34) 14(6.63,3.34)
  round 2.5 hole 1.7 mask+0.05: 15(7.75,10.45) 16(-7.75,10.45)
  round 1 hole 3.2 unplated mask+0.1: 17(-5.715,7.4) 18(5.715,7.4)
  Multi-Layer keep-out circle w0.01: c5.715,7.4 r1.9
  Multi-Layer keep-out circle w0.01: c-5.715,7.4 r1.9
  silkscreen extent -11.26,-3.5 11.26,18.34, body extent -11.4,-3.5 11.39,18.34, height 17
CON_SAMTEC_CLM-120-02-L-D_Reverse-to-Camera [mm] "not in line with Samtec spec"
  rect 1.85x0.7 smd mask+0.05: 1(-1.275,9.5) 2(1.275,9.5) 3(-1.275,8.5) 4(1.275,8.5) 5(-1.275,7.5) 6(1.275,7.5) 7(-1.275,6.5) 8(1.275,6.5) 9(-1.275,5.5) 10(1.275,5.5) 11(-1.275,4.5) 12(1.275,4.5) 13(-1.275,3.5) 14(1.275,3.5) 15(-1.275,2.5) 16(1.275,2.5) 17(-1.275,1.5) 18(1.275,1.5) 19(-1.275,0.5) 20(1.275,0.5) 21(-1.275,-0.5) 22(1.275,-0.5) 23(-1.275,-1.5) 24(1.275,-1.5) 25(-1.275,-2.5) 26(1.275,-2.5) 27(-1.275,-3.5) 28(1.275,-3.5) 29(-1.275,-4.5) 30(1.275,-4.5) 31(-1.275,-5.5) 32(1.275,-5.5) 33(-1.275,-6.5) 34(1.275,-6.5) 35(-1.275,-7.5) 36(1.275,-7.5) 37(-1.275,-8.5) 38(1.275,-8.5) 39(-1.275,-9.5) 40(1.275,-9.5)
  round 6 hole 3.2 mask+0.1: 41(0,15.27) 42(0,-15.27)
  silkscreen extent -16.5,-19 6,21, body extent -16.5,-19 6,21, height 5.69
CON_SAMTEC_ERF8-030-070-L-DV-TR_MOD-B2123A [mm] "RECEPTACLE MODULE B2123A"
  rect 1.1x0.5 smd mask+0.05: 1(2.25,-11.6) 2(-2.25,-11.6) 3(2.25,-10.8) 4(-2.25,-10.8) 5(2.25,-10) 6(-2.25,-10) 7(2.25,-9.2) 8(-2.25,-9.2) 9(2.25,-8.4) 10(-2.25,-8.4) 11(2.25,-7.6) 12(-2.25,-7.6) 13(2.25,-6.8) 14(-2.25,-6.8) 15(2.25,-6) 16(-2.25,-6) 17(2.25,-5.2) 18(-2.25,-5.2) 19(2.25,-4.4) 20(-2.25,-4.4) 21(2.25,-3.6) 22(-2.25,-3.6) 23(2.25,-2.8) 24(-2.25,-2.8) 25(2.25,-2) 26(-2.25,-2) 27(2.25,-1.2) 28(-2.25,-1.2) 29(2.25,-0.4) 30(-2.25,-0.4) 31(2.25,0.4) 32(-2.25,0.4) 33(2.25,1.2) 34(-2.25,1.2) 35(2.25,2) 36(-2.25,2) 37(2.25,2.8) 38(-2.25,2.8) 39(2.25,3.6) 40(-2.25,3.6) 41(2.25,4.4) 42(-2.25,4.4) 43(2.25,5.2) 44(-2.25,5.2) 45(2.25,6) 46(-2.25,6) 47(2.25,6.8) 48(-2.25,6.8) 49(2.25,7.6) 50(-2.25,7.6) 51(2.25,8.4) 52(-2.25,8.4) 53(2.25,9.2) 54(-2.25,9.2) 55(2.25,10) 56(-2.25,10) 57(2.25,10.8) 58(-2.25,10.8) 59(2.25,11.6) 60(-2.25,11.6)
  round 0 hole 1.5 unplated mask+0.1: NHP2(-1.5,13.4) NPH1(-1.5,-13.4)
  round 5 hole 3.5 mask+0.1: PTH1(7,15) PTH2(-60,15) PTH3(-60,-15) PTH4(7,-15)
  Multi-Layer keep-out circle w0.01: c-1.5,13.4 r0.951
  Multi-Layer keep-out circle w0.01: c-1.5,-13.4 r0.951
  silkscreen extent -70,-20 12,20, body extent -70,-20 12,20, height 17.6
CON_SAMTEC_QSH-030-01-F-D-A [mm]
  rect 0.3x2.27 smd mask+0.05: 1(7.25,2.87) 2(7.25,-2.87) 3(6.75,2.87) 4(6.75,-2.87) 5(6.25,2.87) 6(6.25,-2.87) 7(5.75,2.87) 8(5.75,-2.87) 9(5.25,2.87) 10(5.25,-2.87) 11(4.75,2.87) 12(4.75,-2.87) 13(4.25,2.87) 14(4.25,-2.87) 15(3.75,2.87) 16(3.75,-2.87) 17(3.25,2.87) 18(3.25,-2.87) 19(2.75,2.87) 20(2.75,-2.87) 21(2.25,2.87) 22(2.25,-2.87) 23(1.75,2.87) 24(1.75,-2.87) 25(1.25,2.87) 26(1.25,-2.87) 27(0.75,2.87) 28(0.75,-2.87) 29(0.25,2.87) 30(0.25,-2.87) 31(-0.25,2.87) 32(-0.25,-2.87) 33(-0.75,2.87) 34(-0.75,-2.87) 35(-1.25,2.87) 36(-1.25,-2.87) 37(-1.75,2.87) 38(-1.75,-2.87) 39(-2.25,2.87) 40(-2.25,-2.87) 41(-2.75,2.87) 42(-2.75,-2.87) 43(-3.25,2.87) 44(-3.25,-2.87) 45(-3.75,2.87) 46(-3.75,-2.87) 47(-4.25,2.87) 48(-4.25,-2.87) 49(-4.75,2.87) 50(-4.75,-2.87) 51(-5.25,2.87) 52(-5.25,-2.87) 53(-5.75,2.87) 54(-5.75,-2.87) 55(-6.25,2.87) 56(-6.25,-2.87) 57(-6.75,2.87) 58(-6.75,-2.87) 59(-7.25,2.87) 60(-7.25,-2.87)
  rect 2.54x0.43 smd mask+0.05: 61(8.063,0) 64(-8.063,0)
  rect 4.7x0.43 smd mask+0.05: 62(3.175,0) 63(-3.175,0)
  round 0.5 hole 1.05 unplated mask+0.1: 65(-10.065,-2.67) 66(10.065,-2.67)
  Multi-Layer keep-out circle w0.01: c-10.065,-2.67 r0.801
  Multi-Layer keep-out circle w0.01: c10.065,-2.67 r0.801
  silkscreen extent -10.8,-3.7 10.8,3.7, body extent -10.8,-3.75 10.8,3.75, height 3.26
CON_SAMTEC_QSH-030-01-F-D-A_LCD-MB1230 [mm] "LCD MB1230 DSI ROCKTECH"
  rect 0.3x2.27 smd mask+0.05: 1(-7.25,-2.87) 2(-7.25,2.87) 3(-6.75,-2.87) 4(-6.75,2.87) 5(-6.25,-2.87) 6(-6.25,2.87) 7(-5.75,-2.87) 8(-5.75,2.87) 9(-5.25,-2.87) 10(-5.25,2.87) 11(-4.75,-2.87) 12(-4.75,2.87) 13(-4.25,-2.87) 14(-4.25,2.87) 15(-3.75,-2.87) 16(-3.75,2.87) 17(-3.25,-2.87) 18(-3.25,2.87) 19(-2.75,-2.87) 20(-2.75,2.87) 21(-2.25,-2.87) 22(-2.25,2.87) 23(-1.75,-2.87) 24(-1.75,2.87) 25(-1.25,-2.87) 26(-1.25,2.87) 27(-0.75,-2.87) 28(-0.75,2.87) 29(-0.25,-2.87) 30(-0.25,2.87) 31(0.25,-2.87) 32(0.25,2.87) 33(0.75,-2.87) 34(0.75,2.87) 35(1.25,-2.87) 36(1.25,2.87) 37(1.75,-2.87) 38(1.75,2.87) 39(2.25,-2.87) 40(2.25,2.87) 41(2.75,-2.87) 42(2.75,2.87) 43(3.25,-2.87) 44(3.25,2.87) 45(3.75,-2.87) 46(3.75,2.87) 47(4.25,-2.87) 48(4.25,2.87) 49(4.75,-2.87) 50(4.75,2.87) 51(5.25,-2.87) 52(5.25,2.87) 53(5.75,-2.87) 54(5.75,2.87) 55(6.25,-2.87) 56(6.25,2.87) 57(6.75,-2.87) 58(6.75,2.87) 59(7.25,-2.87) 60(7.25,2.87)
  rect 2.54x0.43 smd mask+0.05: 61(-8.063,0) 64(8.063,0)
  rect 4.7x0.43 smd mask+0.05: 62(-3.175,0) 63(3.175,0)
  round 0.5 hole 1.05 unplated mask+0.1: 65(10.065,2.67) 66(-10.065,2.67)
  round 5 hole 3.2 mask+0.1: PTH3(-49.75,60.6) PTH4(93.25,60.6)
  Multi-Layer keep-out circle w0.01: c10.065,2.67 r0.801
  Multi-Layer keep-out circle w0.01: c-10.065,2.67 r0.801
  silkscreen extent -54.3,-7.4 97.7,72.6, body extent -54.25,-7.4 97.75,72.6, height 13
CON_SAMTEC_QSH-060-01-L-D-A [mm]
  rect 0.3x2.27 smd mask+0.05: 1(-17.25,-2.87) 2(-17.25,2.87) 3(-16.75,-2.87) 4(-16.75,2.87) 5(-16.25,-2.87) 6(-16.25,2.87) 7(-15.75,-2.87) 8(-15.75,2.87) 9(-15.25,-2.87) 10(-15.25,2.87) 11(-14.75,-2.87) 12(-14.75,2.87) 13(-14.25,-2.87) 14(-14.25,2.87) 15(-13.75,-2.87) 16(-13.75,2.87) 17(-13.25,-2.87) 18(-13.25,2.87) 19(-12.75,-2.87) 20(-12.75,2.87) 21(-12.25,-2.87) 22(-12.25,2.87) 23(-11.75,-2.87) 24(-11.75,2.87) 25(-11.25,-2.87) 26(-11.25,2.87) 27(-10.75,-2.87) 28(-10.75,2.87) 29(-10.25,-2.87) 30(-10.25,2.87) 31(-9.75,-2.87) 32(-9.75,2.87) 33(-9.25,-2.87) 34(-9.25,2.87) 35(-8.75,-2.87) 36(-8.75,2.87) 37(-8.25,-2.87) 38(-8.25,2.87) 39(-7.75,-2.87) 40(-7.75,2.87) 41(-7.25,-2.87) 42(-7.25,2.87) 43(-6.75,-2.87) 44(-6.75,2.87) 45(-6.25,-2.87) 46(-6.25,2.87) 47(-5.75,-2.87) 48(-5.75,2.87) 49(-5.25,-2.87) 50(-5.25,2.87) 51(-4.75,-2.87) 52(-4.75,2.87) 53(-4.25,-2.87) 54(-4.25,2.87) 55(-3.75,-2.87) 56(-3.75,2.87) 57(-3.25,-2.87) 58(-3.25,2.87) 59(-2.75,-2.87) 60(-2.75,2.87) 61(2.75,-2.87) 62(2.75,2.87) 63(3.25,-2.87) 64(3.25,2.87) 65(3.75,-2.87) 66(3.75,2.87) 67(4.25,-2.87) 68(4.25,2.87) 69(4.75,-2.87) 70(4.75,2.87) 71(5.25,-2.87) 72(5.25,2.87) 73(5.75,-2.87) 74(5.75,2.87) 75(6.25,-2.87) 76(6.25,2.87) 77(6.75,-2.87) 78(6.75,2.87) 79(7.25,-2.87) 80(7.25,2.87) 81(7.75,-2.87) 82(7.75,2.87) 83(8.25,-2.87) 84(8.25,2.87) 85(8.75,-2.87) 86(8.75,2.87) 87(9.25,-2.87) 88(9.25,2.87) 89(9.75,-2.87) 90(9.75,2.87) 91(10.25,-2.87) 92(10.25,2.87) 93(10.75,-2.87) 94(10.75,2.87) 95(11.25,-2.87) 96(11.25,2.87) 97(11.75,-2.87) 98(11.75,2.87) 99(12.25,-2.87) 100(12.25,2.87) 101(12.75,-2.87) 102(12.75,2.87) 103(13.25,-2.87) 104(13.25,2.87) 105(13.75,-2.87) 106(13.75,2.87) 107(14.25,-2.87) 108(14.25,2.87) 109(14.75,-2.87) 110(14.75,2.87) 111(15.25,-2.87) 112(15.25,2.87) 113(15.75,-2.87) 114(15.75,2.87) 115(16.25,-2.87) 116(16.25,2.87) 117(16.75,-2.87) 118(16.75,2.87) 119(17.25,-2.87) 120(17.25,2.87)
  rect 2.54x0.43 smd mask+0.05: 121(-18.062,0) 124(-1.937,0) 125(1.937,0) 128(18.062,0)
  rect 4.7x0.43 smd mask+0.05: 122(-13.175,0) 123(-6.825,0) 126(6.825,0) 127(13.175,0)
  round 0.5 hole 1.05 unplated mask+0.1: 129(-20.065,2.67) 130(20.065,2.67)
  Multi-Layer keep-out circle w0.01: c-20.065,2.67 r0.8
  Multi-Layer keep-out circle w0.01: c20.065,2.67 r0.8
  silkscreen extent -20.73,-3.7 20.73,3.7, body extent -20.65,-3.75 20.66,3.75, height 3.25
CON_SAMTEC_SSM-104-L-DH [mm]
  rect 1.2x3.4 smd mask+0.05: 1(3.81,-5) 2(3.81,5) 3(1.27,-5) 4(1.27,5) 5(-1.27,-5) 6(-1.27,5) 7(-3.81,-5) 8(-3.81,5)
  silkscreen extent -5.08,-4.06 5.08,4.06, body extent -5.08,-5.46 5.11,5.46, height 5.92
CON_SAMTEC_TST-117-01-T-D [mm]
  rect 1.8x1.8 hole 1.1 mask+0.05: 1(-20.32,-1.27)
  round 1.8 hole 1.1 mask+0.05: 2(-20.32,1.27) 3(-17.78,-1.27) 4(-17.78,1.27) 5(-15.24,-1.27) 6(-15.24,1.27) 7(-12.7,-1.27) 8(-12.7,1.27) 9(-10.16,-1.27) 10(-10.16,1.27) 11(-7.62,-1.27) 12(-7.62,1.27) 13(-5.08,-1.27) 14(-5.08,1.27) 15(-2.54,-1.27) 16(-2.54,1.27) 17(0,-1.27) 18(0,1.27) 19(2.54,-1.27) 20(2.54,1.27) 21(5.08,-1.27) 22(5.08,1.27) 23(7.62,-1.27) 24(7.62,1.27) 25(10.16,-1.27) 26(10.16,1.27) 27(12.7,-1.27) 28(12.7,1.27) 29(15.24,-1.27) 30(15.24,1.27) 31(17.78,-1.27) 32(17.78,1.27) 33(20.32,-1.27) 34(20.32,1.27)
  silkscreen extent -25.4,-4.83 25.4,4.83, body extent -25.4,-4.83 25.4,4.83, height 9.27
CON_SAMTEC_TSW-102-07-G-S [mm]
  rect 1.85x1.85 / inner round 1.85 / far side rect 1.85x1.85 hole 1 mask+0.05: 1(-1.27,0)
  round 1.85 hole 1 mask+0.05: 2(1.27,0)
  silkscreen extent -2.58,-1.3 2.58,1.3, body extent -2.67,-1.3 2.58,1.3, height 8.38
CON_SAMTEC_TSW-103-07-F-S [mm]
  rect 1.85x1.85 / inner round 1.85 / far side rect 1.85x1.85 hole 1 mask+0.05: 1(-2.54,0)
  round 1.85 hole 1 mask+0.05: 2(0,0) 3(2.54,0)
  silkscreen extent -3.85,-1.3 3.85,1.3, body extent -3.91,-1.37 3.91,1.37, height 8.38
CON_SAMTEC_TSW-104-07-G-S [mm]
  rect 1.85x1.85 / inner round 1.85 / far side rect 1.85x1.85 hole 1 mask+0.05: 1(-3.81,0)
  round 1.85 hole 1 mask+0.05: 2(-1.27,0) 3(1.27,0) 4(3.81,0)
  silkscreen extent -5.12,-1.3 5.12,1.3, body extent -5.21,-1.37 5.18,1.37, height 8.38
CON_SAMTEC_TSW-120-07-G-D [mm]
  rect 1.85x1.85 / inner round 1.85 / far side rect 1.85x1.85 hole 1 mask+0.05: 1(-24.13,-1.27)
  round 1.85 hole 1 mask+0.05: 2(-24.13,1.27) 3(-21.59,-1.27) 4(-21.59,1.27) 5(-19.05,-1.27) 6(-19.05,1.27) 7(-16.51,-1.27) 8(-16.51,1.27) 9(-13.97,-1.27) 10(-13.97,1.27) 11(-11.43,-1.27) 12(-11.43,1.27) 13(-8.89,-1.27) 14(-8.89,1.27) 15(-6.35,-1.27) 16(-6.35,1.27) 17(-3.81,-1.27) 18(-3.81,1.27) 19(-1.27,-1.27) 20(-1.27,1.27) 21(1.27,-1.27) 22(1.27,1.27) 23(3.81,-1.27) 24(3.81,1.27) 25(6.35,-1.27) 26(6.35,1.27) 27(8.89,-1.27) 28(8.89,1.27) 29(11.43,-1.27) 30(11.43,1.27) 31(13.97,-1.27) 32(13.97,1.27) 33(16.51,-1.27) 34(16.51,1.27) 35(19.05,-1.27) 36(19.05,1.27) 37(21.59,-1.27) 38(21.59,1.27) 39(24.13,-1.27) 40(24.13,1.27)
  silkscreen extent -25.4,-2.54 25.4,2.54, body extent -25.4,-2.55 25.4,2.54, height 8.38
CON_SMARTCARD_CONCRAFT_093A-65-08A [mm]
  round 1 hole 2.15 unplated mask+0.2: 11(-20.89,3.99) 12(23.56,24.31)
  rect 1x1.75 smd mask+0.05: C1(-6.92,26.97) C2(-4.38,26.97) C3(-1.84,26.97) C4(0.7,26.97) C5(-6.92,1.33) C6(-4.38,1.33) C7(-1.84,1.33) C8(0.7,1.33) S1(5.78,19.64) S2(8.32,19.64)
  silkscreen extent -28,0 28,31.1, body extent -28.98,0 28.82,32.15, height 3.64
CON_SMD-RCA-SOCKET_CUI_RCJ-013-SMT [mm]
  oval 1.8x2.7 hole 1 slot 1.6 at 90 deg mask+0.05: 1(0,0)
  rect 2.2x2.5 smd mask+0.05: 2(6,-6.35) 3(6,6.35)
  rect 2.2x2.6 smd mask+0.05: 4(6,0)
  silkscreen extent -8.5,-5.5 5.1,5.5, body extent -8.5,-7 6.55,7, height 12.1
CON_USBMICROAB_MOLEX_47590-0001_H3 [mm]
  rect 0.4x1.35 smd mask+0.05: 1(1.3,4.125) 2(0.65,4.125) 3(0,4.125) 4(-0.65,4.125) 5(-1.3,4.125)
  oval 1.05x1.25 hole 0.65 slot 0.85 at 90 deg mask+0.05: 6(-2.225,4.45) 7(2.225,4.45)
  rrect50% 1.375x1.9 hole 0.6 slot 1.3 at 90 deg copper offset 0.188,0 mask+0.05: 8(-4.175,1.45)
  rrect50% 1.375x1.9 hole 0.6 slot 1.3 at 90 deg copper offset -0.188,0 mask+0.05: 9(4.175,1.45)
  rect 2.9x1.9 smd mask+0.05: 10(0,1.45)
  oval 0.85x2.425 hole 0.85 slot 2.425 at 90 deg unplated mask+0.1: 11(-2.375,0.8) 12(2.375,0.8)
  silkscreen extent -4.1,-1.3 4.1,4.3, body extent -4.33,-1.36 4.32,4.6, height 3
CPOL_TAJ-A_1206_H180 [mm]
  rect 1.45x1.6 smd mask+0.05: 1(-1.175,0) 2(1.175,0)
  silkscreen extent -2.15,-1.05 1.7,1.05, body extent -1.7,-0.9 1.7,0.9, height 1.8
CPOL_TAJ-C_2312_H2P6 [mm]
  rect 2.2x2.6 smd mask+0.05: 1(-2.3,0) 2(2.3,0)
  silkscreen extent -3.6,-1.85 3.1,1.85, body extent -3.1,-1.7 3.1,1.7, height 2.8
CRY_NX3225HA_4P [mm]
  rect 1.4x1.2 smd mask+0.05: 1(-1.1,-0.8) 2(1.1,-0.8) 3(1.1,0.8) 4(-1.1,0.8)
  silkscreen extent -1.9,-1.5 1.65,1.3, body extent -1.66,-1.31 1.66,1.31, height 0.91
CRY_TXC_7A-SERIES_5X3P2_H1P2_2P [mm]
  rect 1.7x2.4 smd mask+0.05: 1(-1.85,0) 2(1.85,0)
  silkscreen extent -2.6,-1.7 2.6,1.7, body extent -2.6,-1.7 2.6,1.7, height 1.35
DIO_SOD323 [mm]
  rect 1.06x0.54 smd mask+0.05: 1(-1.07,0) 2(1.07,0)
  silkscreen extent -0.9,-0.72 0.9,0.72, body extent -1.3,-0.78 1.3,0.78, height 1.17
DIO_SOT353 [mm]
  rect 0.42x0.6 smd mask+0.05: 1(-0.65,-0.95) 2(0,-0.95) 3(0.65,-0.95) 4(0.65,0.95) 5(-0.65,0.95)
  silkscreen extent -1.17,-0.75 1.17,0.75, body extent -1.23,-1.2 1.23,1.2, height 1.1
ESD_SOT23 [mm]
  rect 1x1.4 smd mask+0.05: 1(-0.95,-1.1) 2(0.95,-1.1) 3(0,1.1)
  silkscreen extent -1.63,-0.82 1.63,0.82, body extent -1.56,-1.5 1.56,1.5, height 1.4
ESD_SOT323-5L [mm]
  rect 0.4x1.2 smd mask+0.05: 1(-0.65,-0.85) 2(0,-0.85) 3(0.65,-0.85) 4(0.65,0.85) 5(-0.65,0.85)
  silkscreen extent -1.22,-1.11 1.22,0.77, body extent -1.15,-1.05 1.15,1.05, height 1.1
ESD_UQFN-8L_2P5X1P2_P050 [mm]
  rect 0.2x0.2 smd mask+0.05: 1(-0.75,-0.5) 4(0.75,-0.5) 5(0.75,0.5) 8(-0.75,0.5)
  rect 0.2x0.6 smd mask+0.05: 2(-0.25,-0.5) 3(0.25,-0.5) 6(0.25,0.5) 7(-0.25,0.5)
  Top Layer region: -0.65,-0.8 -0.65,-0.2 -1.05,-0.2 -1.05,-0.4 -0.85,-0.4 -0.85,-0.8 -0.65,-0.8
  Top Layer region: 0.65,-0.2 1.05,-0.2 1.05,-0.4 0.85,-0.4 0.85,-0.8 0.65,-0.8 0.65,-0.2
  Top Layer region: 0.65,0.2 1.05,0.2 1.05,0.4 0.85,0.4 0.85,0.8 0.65,0.8 0.65,0.2
  Top Layer region: -0.65,0.8 -0.65,0.2 -1.05,0.2 -1.05,0.4 -0.85,0.4 -0.85,0.8 -0.65,0.8
  silkscreen extent -1.28,-0.63 1.28,0.63, body extent -1.28,-0.63 1.28,0.63, height 0.6
FIL_0603_H065 [mm]
  rect 0.8x0.95 smd mask+0.05: 1(-0.8,0) 2(0.8,0)
  silkscreen extent -1.33,-0.6 1.33,0.6, body extent -0.87,-0.47 0.87,0.47, height 0.65
ICC_BGA24_5X5-BALL-ARRAY_6X8_P1 [mm]
  round 0.45 smd mask+0.05: A2(-1,2) A3(0,2) A4(1,2) A5(2,2) B1(-2,1) B2(-1,1) B3(0,1) B4(1,1) B5(2,1) C1(-2,0) C2(-1,0) C3(0,0) C4(1,0) C5(2,0) D1(-2,-1) D2(-1,-1) D3(0,-1) D4(1,-1) D5(2,-1) E1(-2,-2) E2(-1,-2) E3(0,-2) E4(1,-2) E5(2,-2)
  silkscreen extent -3.05,-4.05 3.05,4.05, body extent -3.05,-4.05 3.05,4.05, height 1.2
ICC_LQFP48_7X7_P050 [mm]
  rect 0.3x1.2 smd mask+0.05: 1(-2.75,-4.25) 2(-2.25,-4.25) 3(-1.75,-4.25) 4(-1.25,-4.25) 5(-0.75,-4.25) 6(-0.25,-4.25) 7(0.25,-4.25) 8(0.75,-4.25) 9(1.25,-4.25) 10(1.75,-4.25) 11(2.25,-4.25) 12(2.75,-4.25) 25(2.75,4.25) 26(2.25,4.25) 27(1.75,4.25) 28(1.25,4.25) 29(0.75,4.25) 30(0.25,4.25) 31(-0.25,4.25) 32(-0.75,4.25) 33(-1.25,4.25) 34(-1.75,4.25) 35(-2.25,4.25) 36(-2.75,4.25)
  rect 1.2x0.3 smd mask+0.05: 13(4.25,-2.75) 14(4.25,-2.25) 15(4.25,-1.75) 16(4.25,-1.25) 17(4.25,-0.75) 18(4.25,-0.25) 19(4.25,0.25) 20(4.25,0.75) 21(4.25,1.25) 22(4.25,1.75) 23(4.25,2.25) 24(4.25,2.75) 37(-4.25,2.75) 38(-4.25,2.25) 39(-4.25,1.75) 40(-4.25,1.25) 41(-4.25,0.75) 42(-4.25,0.25) 43(-4.25,-0.25) 44(-4.25,-0.75) 45(-4.25,-1.25) 46(-4.25,-1.75) 47(-4.25,-2.25) 48(-4.25,-2.75)
  silkscreen extent -3.52,-3.52 3.52,3.52, body extent -4.5,-4.5 4.5,4.5, height 1.6
ICC_QFN36-EPAD_6X6_P050 [mm]
  rrect50% 0.3x0.9 smd mask+0.05: 1(-2,-2.75) 9(2,-2.75) 19(2,2.75) 27(-2,2.75)
  rect 0.3x0.9 smd mask+0.05: 2(-1.5,-2.75) 3(-1,-2.75) 4(-0.5,-2.75) 5(0,-2.75) 6(0.5,-2.75) 7(1,-2.75) 8(1.5,-2.75) 20(1.5,2.75) 21(1,2.75) 22(0.5,2.75) 23(0,2.75) 24(-0.5,2.75) 25(-1,2.75) 26(-1.5,2.75)
  rrect50% 0.9x0.3 smd mask+0.05: 10(2.75,-2) 18(2.75,2) 28(-2.75,2) 36(-2.75,-2)
  rect 0.9x0.3 smd mask+0.05: 11(2.75,-1.5) 12(2.75,-1) 13(2.75,-0.5) 14(2.75,0) 15(2.75,0.5) 16(2.75,1) 17(2.75,1.5) 29(-2.75,1.5) 30(-2.75,1) 31(-2.75,0.5) 32(-2.75,0) 33(-2.75,-0.5) 34(-2.75,-1) 35(-2.75,-1.5)
  rect 3.9x3.9 smd mask+0.05: 37(0,0)
  silkscreen extent -3.15,-3.15 3.15,3.15, body extent -3.06,-3.06 3.06,3.06, height 1
ICC_QFN64-EPAD_9X9_P050 [mm]
  oval 0.8x0.28 smd mask+0.05: 1(-4.4,3.75) 2(-4.4,3.25) 3(-4.4,2.75) 4(-4.4,2.25) 5(-4.4,1.75) 6(-4.4,1.25) 7(-4.4,0.75) 8(-4.4,0.25) 9(-4.4,-0.25) 10(-4.4,-0.75) 11(-4.4,-1.25) 12(-4.4,-1.75) 13(-4.4,-2.25) 14(-4.4,-2.75) 15(-4.4,-3.25) 16(-4.4,-3.75) 33(4.4,-3.75) 34(4.4,-3.25) 35(4.4,-2.75) 36(4.4,-2.25) 37(4.4,-1.75) 38(4.4,-1.25) 39(4.4,-0.75) 40(4.4,-0.25) 41(4.4,0.25) 42(4.4,0.75) 43(4.4,1.25) 44(4.4,1.75) 45(4.4,2.25) 46(4.4,2.75) 47(4.4,3.25) 48(4.4,3.75)
  oval 0.28x0.8 smd mask+0.05: 17(-3.75,-4.4) 18(-3.25,-4.4) 19(-2.75,-4.4) 20(-2.25,-4.4) 21(-1.75,-4.4) 22(-1.25,-4.4) 23(-0.75,-4.4) 24(-0.25,-4.4) 25(0.25,-4.4) 26(0.75,-4.4) 27(1.25,-4.4) 28(1.75,-4.4) 29(2.25,-4.4) 30(2.75,-4.4) 31(3.25,-4.4) 32(3.75,-4.4) 49(3.75,4.4) 50(3.25,4.4) 51(2.75,4.4) 52(2.25,4.4) 53(1.75,4.4) 54(1.25,4.4) 55(0.75,4.4) 56(0.25,4.4) 57(-0.25,4.4) 58(-0.75,4.4) 59(-1.25,4.4) 60(-1.75,4.4) 61(-2.25,4.4) 62(-2.75,4.4) 63(-3.25,4.4) 64(-3.75,4.4)
  rect 5.5x5.5 smd mask+0.05: 65(0,0)
  silkscreen extent -4.65,-4.65 4.65,4.65, body extent -4.58,-4.58 4.58,4.58, height 1
ICC_SO8_5X4_P127 [mm]
  rect 0.7x1.75 smd mask+0.05: 1(-1.905,-2.375) 2(-0.635,-2.375) 3(0.635,-2.375) 4(1.905,-2.375) 5(1.905,2.375) 6(0.635,2.375) 7(-0.635,2.375) 8(-1.905,2.375)
  silkscreen extent -2.58,-2 2.58,2, body extent -2.57,-3 2.57,3, height 1.75
ICC_SO28_18P10X7P60_P127 [mm]
  rect 0.8x2.02 smd mask+0.05: 1(-8.255,-4.59) 2(-6.985,-4.59) 3(-5.715,-4.59) 4(-4.445,-4.59) 5(-3.175,-4.59) 6(-1.905,-4.59) 7(-0.635,-4.59) 8(0.635,-4.59) 9(1.905,-4.59) 10(3.175,-4.59) 11(4.445,-4.59) 12(5.715,-4.59) 13(6.985,-4.59) 14(8.255,-4.59) 15(8.255,4.59) 16(6.985,4.59) 17(5.715,4.59) 18(4.445,4.59) 19(3.175,4.59) 20(1.905,4.59) 21(0.635,4.59) 22(-0.635,4.59) 23(-1.905,4.59) 24(-3.175,4.59) 25(-4.445,4.59) 26(-5.715,4.59) 27(-6.985,4.59) 28(-8.255,4.59)
  silkscreen extent -9.05,-3.8 9.05,3.8, body extent -9.05,-5.16 9.05,5.16, height 2.65
ICC_SSOP28_10P2X5P3_P065 [mm]
  rect 0.45x1.9 smd mask+0.05: 1(-4.225,-3.45) 2(-3.575,-3.45) 3(-2.925,-3.45) 4(-2.275,-3.45) 5(-1.625,-3.45) 6(-0.975,-3.45) 7(-0.325,-3.45) 8(0.325,-3.45) 9(0.975,-3.45) 10(1.625,-3.45) 11(2.275,-3.45) 12(2.925,-3.45) 13(3.575,-3.45) 14(4.225,-3.45) 15(4.225,3.45) 16(3.575,3.45) 17(2.925,3.45) 18(2.275,3.45) 19(1.625,3.45) 20(0.975,3.45) 21(0.325,3.45) 22(-0.325,3.45) 23(-0.975,3.45) 24(-1.625,3.45) 25(-2.275,3.45) 26(-2.925,3.45) 27(-3.575,3.45) 28(-4.225,3.45)
  silkscreen extent -5.25,-2.8 5.25,2.8, body extent -5.25,-3.9 5.25,3.9, height 2
ICC_VFBGA63_9X11_P080 [mm]
  round 0.32 smd mask+0.05: A1(-3.6,4.4) A2(-2.8,4.4) A9(2.8,4.4) A10(3.6,4.4) B1(-3.6,3.6) B9(2.8,3.6) B10(3.6,3.6) C3(-2,2.8) C4(-1.2,2.8) C5(-0.4,2.8) C6(0.4,2.8) C7(1.2,2.8) C8(2,2.8) D3(-2,2) D4(-1.2,2) D5(-0.4,2) D6(0.4,2) D7(1.2,2) D8(2,2) E3(-2,1.2) E4(-1.2,1.2) E5(-0.4,1.2) E6(0.4,1.2) E7(1.2,1.2) E8(2,1.2) F3(-2,0.4) F4(-1.2,0.4) F5(-0.4,0.4) F6(0.4,0.4) F7(1.2,0.4) F8(2,0.4) G3(-2,-0.4) G4(-1.2,-0.4) G5(-0.4,-0.4) G6(0.4,-0.4) G7(1.2,-0.4) G8(2,-0.4) H3(-2,-1.2) H4(-1.2,-1.2) H5(-0.4,-1.2) H6(0.4,-1.2) H7(1.2,-1.2) H8(2,-1.2) J3(-2,-2) J4(-1.2,-2) J5(-0.4,-2) J6(0.4,-2) J7(1.2,-2) J8(2,-2) K3(-2,-2.8) K4(-1.2,-2.8) K5(-0.4,-2.8) K6(0.4,-2.8) K7(1.2,-2.8) K8(2,-2.8) L1(-3.6,-3.6) L2(-2.8,-3.6) L9(2.8,-3.6) L10(3.6,-3.6) M1(-3.6,-4.4) M2(-2.8,-4.4) M9(2.8,-4.4) M10(3.6,-4.4)
  silkscreen extent -4.75,-5.65 4.65,5.75, body extent -4.55,-5.55 4.55,5.55, height 1.24
ICC_W-CSP-BGA72_4P511X4P023_P050 [mm]
  round 0.25 smd mask+0.05: A1(-2,1.75) A2(-1.5,1.75) A3(-1,1.75) A4(-0.5,1.75) A5(0,1.75) A6(0.5,1.75) A7(1,1.75) A8(1.5,1.75) A9(2,1.75) B1(-2,1.25) B2(-1.5,1.25) B3(-1,1.25) B4(-0.5,1.25) B5(0,1.25) B6(0.5,1.25) B7(1,1.25) B8(1.5,1.25) B9(2,1.25) C1(-2,0.75) C2(-1.5,0.75) C3(-1,0.75) C4(-0.5,0.75) C5(0,0.75) C6(0.5,0.75) C7(1,0.75) C8(1.5,0.75) C9(2,0.75) D1(-2,0.25) D2(-1.5,0.25) D3(-1,0.25) D4(-0.5,0.25) D5(0,0.25) D6(0.5,0.25) D7(1,0.25) D8(1.5,0.25) D9(2,0.25) E1(-2,-0.25) E2(-1.5,-0.25) E3(-1,-0.25) E4(-0.5,-0.25) E5(0,-0.25) E6(0.5,-0.25) E7(1,-0.25) E8(1.5,-0.25) E9(2,-0.25) F1(-2,-0.75) F2(-1.5,-0.75) F3(-1,-0.75) F4(-0.5,-0.75) F5(0,-0.75) F6(0.5,-0.75) F7(1,-0.75) F8(1.5,-0.75) F9(2,-0.75) G1(-2,-1.25) G2(-1.5,-1.25) G3(-1,-1.25) G4(-0.5,-1.25) G5(0,-1.25) G6(0.5,-1.25) G7(1,-1.25) G8(1.5,-1.25) G9(2,-1.25) H1(-2,-1.75) H2(-1.5,-1.75) H3(-1,-1.75) H4(-0.5,-1.75) H5(0,-1.75) H6(0.5,-1.75) H7(1,-1.75) H8(1.5,-1.75) H9(2,-1.75)
  silkscreen extent -2.42,-2.03 2.28,2.17, body extent -2.28,-2.04 2.28,2.04, height 0.78
L0603 [mm]
  rect 0.8x0.95 smd mask+0.05: 1(-0.8,0) 2(0.8,0)
  silkscreen extent -1.33,-0.6 1.33,0.6, body extent -0.87,-0.47 0.87,0.47, height 0.95
L1210_LQH [mm]
  rect 1.7x3.1 smd mask+0.05: 1(-1.1,0) 2(1.1,0)
  silkscreen extent -2.05,-1.65 2.05,1.65, body extent -1.75,-1.36 1.75,1.36, height 2
LED_0603_GREEN [mm]
  rect 0.8x0.8 smd mask+0.05: 1(-0.75,0) 2(0.75,0)
  silkscreen extent -0.25,-0.4 1.25,0.4, body extent -0.8,-0.4 0.8,0.4, height 0.6
LED_0603_RED [mm]
  rect 0.8x0.8 smd mask+0.05: 1(-0.75,0) 2(0.75,0)
  silkscreen extent -0.25,-0.4 1.25,0.4, body extent -0.8,-0.4 0.8,0.4, height 0.6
